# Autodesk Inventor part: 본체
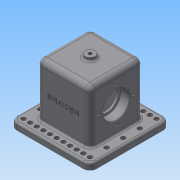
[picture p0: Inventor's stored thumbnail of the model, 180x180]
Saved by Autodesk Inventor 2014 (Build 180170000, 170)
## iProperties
Created: 2018-11
Part Number: 본체
Material: 일반
Document SubType Name: Modeling
Designer: NET
Density: 1 g/cm^3
Appearance: 기본값
Author: NET
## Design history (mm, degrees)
sketch "스케치1"
  geometry: L1 (60, -60)-(-60, -60); L2 (-60, -60)-(-60, 60); L3 (-60, 60)-(60, 60); L4 (60, 60)-(60, -60); 3 further points
  constraints: 8 end point, 2 midpoint, 2 parallel, 1 horizontal, 1 horizontal alignment, 1 perpendicular, 1 vertical alignment
  dimensions: "d0" = 120 distance of L2.end L3.end; "d1" = 120 distance of L3.end L1.start
extrude "돌출1" new body sketch "스케치1" distance "d2" = 10; taper "d3" = 0 deg
sketch "스케치2"
  geometry: L1 (-40, 40)-(40, 40); L2 (40, 40)-(40, -40); L3 (40, -40)-(-40, -40); L4 (-40, -40)-(-40, 40); 3 further points
  constraints: 8 end point, 2 midpoint, 2 parallel, 2 perpendicular, 1 horizontal, 1 horizontal alignment, 1 vertical alignment
  dimensions: "d4" = 80 distance of L1.start L1.end
extrude "돌출2" join sketch "스케치2" distance "d5" = 80; taper "d6" = 0 deg
node "작업 평면1"
sketch "스케치3"
  geometry: C1 r 7.5 at (0, 0); 1 further point
  constraints: 1 centre point, 1 coincident
  dimensions: "d8" = 15 diameter of C1
extrude "돌출3" join sketch "스케치3" stored distance "d9" = 80; taper "d10" = 0 deg
sketch "스케치4"
  geometry: L1 (60, 60)-(-60, 60) reference; L2 (-23, 30)-(23, 30); L3 (23, 30)-(23, -30); L4 (23, -30)-(-23, -30); L5 (-23, -30)-(-23, 30); 4 further points
  constraints: 8 end point, 3 midpoint, 2 parallel, 1 horizontal, 1 horizontal alignment, 1 perpendicular, 1 vertical alignment
  dimensions: "d11" = 46 distance of L3.end L4.end; "d12" = 60 distance of L2.end L3.end
extrude "돌출4" cut sketch "스케치4" distance "d13" = 80; taper "d14" = 0 deg
sketch "스케치5"
  geometry: C1 r 7.5 at (0, 0) reference; 1 further point
  constraints: 1 coincident
hole "구멍1" sketch "스케치5" at (0, 0) diameter "d15" = 4.917; stored, may be unused: countersink angle "d19" = 90 deg, drill point angle "d21" = 0 deg; dims "d16" = 6, "d17" = 4, "d18" = 2, "d20" = 8
sketch "스케치6"
  geometry: L1 (-40, 48)-(-23, 48); L2 (-60, 0)-(60, 0) reference; L3 (-40, 10)-(-40, 90) reference; L4 (-40, 48)-(-40, 68); L5 (-40, 68)-(-26, 68); L6 (-26, 68)-(-26, 64.5); L7 (-26, 64.5)-(-23, 64.5); L8 (-23, 64.5)-(-23, 48); 1 further point
  constraints: 12 end point, 4 perpendicular, 2 point on line, 1 horizontal
  dimensions: "d24" = 48 distance from line of L2 L1.end; "d25" = 40 diameter of L4.end L1; "d26" = 14 distance of L4.end L5.end; "d27" = 33 diameter of L6.end L1; "d28" = 3 distance of L6.end L7.end
revolve "회전1" sketch "스케치6" stored, may be unused: angle "d29" = 90 deg
sketch "스케치7" dims "d30" = 52
  geometry: C1 r 20 at (40, 38) reference; 6 further points
  constraints: 2 vertical alignment, 1 coincident, 7 other
  dimensions: "d33" = 360 deg dimension on C1.centre point (40, 64) (derived)
hole "구멍2" sketch "스케치7" at (40, 64), (14, 38), (40, 12), (66, 38) diameter "d35" = 3.242; stored, may be unused: countersink angle "d39" = 90 deg, drill point angle "d41" = 118 deg; dims "d36" = 8, "d37" = 4, "d38" = 2, "d40" = 10
fillet "모깎기1" dims "d42" = 0.6
chamfer "모따기1" distance "d43" = 1; stored, may be unused: second distance "d44" = 2, angle "d45" = 45 deg
fillet "모깎기2" dims "d46" = 8
fillet "모깎기3" dims "d47" = 3
fillet "모깎기4" dims "d48" = 10
fillet "모깎기5" dims "d49" = 3
sketch "스케치8" dims "d52" = 10, "d62" = 10
  geometry: L1 (57, 50)-(57, -50) reference; L2 (-50, 57)-(50, 57) reference; L3 (-57, -50)-(-57, 50) reference; L4 (50, -57)-(-50, -57) reference; L5 (0, 57)-(0, -57); L6 (-57, 0)-(57, 0); A1 r 7 centre (-50, 50) between (-50, 57) and (-57, 50) reference; 32 further points
  constraints: 16 symmetric about line, 6 midpoint, 4 end point, 1 coincident, 1 horizontal, 1 vertical, 13 other
  dimensions: "d55" = 25 distance of point (-50, 50) point (-50, 25); "d59" = 10 distance of point (-50, 50) point (-40, 50)
hole "구멍3" sketch "스케치8" diameter "d64" = 6.6; stored, may be unused: countersink angle "d68" = 90 deg, drill point angle "d70" = 118 deg; dims "d65" = 8, "d66" = 4, "d67" = 2, "d69" = 10
sketch "스케치9"
  geometry: L1 (92, -82)-(82, -82) reference; L2 (64, 8)-(0, 8) reference; 3 further points
  constraints: 1 midpoint, 1 vertical alignment, 1 other
  dimensions: "d71" = 48 distance from line of L1 point (32, -34)
feature "엠보싱1" sketch "스케치9" dims "d0" = 120, "d1" = 120, "d72" = 0.5, "d73" = 0
node "솔리드1"
mirror "대칭1"
mirror "대칭2"
other parameters: "d7" = -95
